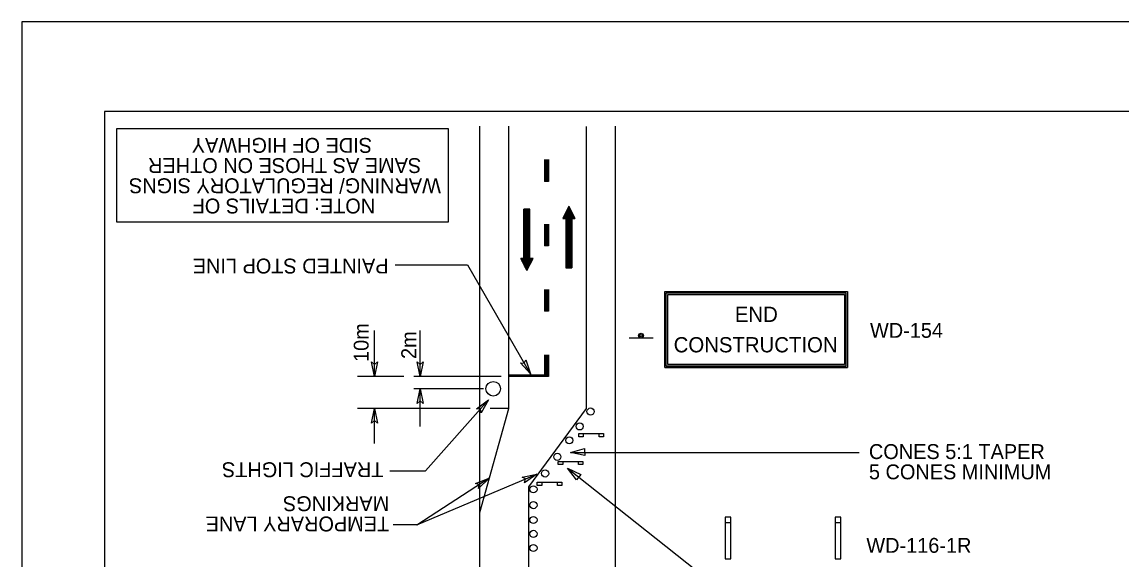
# Model space of a CAD drawing. Extents: x 1062 to 1288, y 239 to 518.
# Drawn here: x 1071.6 to 1204.5, y 453 to 517.9 of the extents above; entities that cross this region are included whole.
import ezdxf

# ---------------------------------------------------------------- set-up
doc = ezdxf.new("R2010")
doc.units = 0
for name, color, linetype in [('Level 10', 7, 'Continuous'), ('Level 17', 7, 'Continuous'), ('Level 44', 7, 'Continuous'), ('Level 5', 7, 'Continuous'), ('Level 60', 7, 'Continuous'), ('Level 7', 7, 'Continuous')]:
    doc.layers.add(name, color=color, linetype=linetype)

# ---------------------------------------------------------------- blocks, each defined once
blk = doc.blocks.new('TAH01')
at = {"layer": 'Level 5'}
blk.add_lwpolyline([(0, 0), (-3, -0.62), (-2.504, 0), (-3, 0.62)], close=True, dxfattribs=at)
blk = doc.blocks.new('LT1')
at = {"layer": 'Level 5'}
blk.add_blockref('TAH01', (0, 0), dxfattribs=at)

msp = doc.modelspace()

# ---------------------------------------------------------------- linework, layer by layer
at = {"layer": 'Level 10'}
for p, q in [((1126.93, 458.61), (1126.93, 505.33)), ((1130.44, 471.19), (1130.44, 505.33)), ((1139.81, 471.19), (1139.81, 505.3)), ((1143.33, 449.55), (1143.33, 505.33)), ((1132.25, 489.35), (1132.25, 495.29)), ((1132.99, 495.29), (1132.25, 495.29)), ((1132.25, 488.6), (1132.25, 495.29)), ((1132.34, 488.42), (1132.34, 495.29)), ((1132.43, 488.23), (1132.43, 495.29)), ((1132.53, 488.05), (1132.53, 495.29)), ((1132.62, 487.86), (1132.62, 495.29)), ((1132.71, 488.05), (1132.71, 495.29)), ((1132.81, 488.23), (1132.81, 495.29)), ((1132.9, 488.42), (1132.9, 495.29)), ((1132.99, 489.35), (1132.99, 495.29)), ((1132.99, 488.6), (1132.99, 495.29)), ((1137.69, 495.64), (1136.95, 494.16)), ((1137.13, 494.53), (1137.13, 494.16)), ((1137.23, 494.71), (1137.23, 494.16)), ((1137.32, 494.9), (1137.32, 488.22)), ((1137.41, 495.08), (1137.41, 488.22)), ((1137.51, 495.27), (1137.51, 488.22)), ((1137.6, 495.45), (1137.6, 488.22)), ((1137.69, 495.64), (1137.69, 488.22)), ((1137.69, 495.64), (1138.43, 494.16)), ((1137.79, 495.45), (1137.79, 488.22)), ((1137.88, 495.27), (1137.88, 488.22)), ((1137.97, 495.08), (1137.97, 488.22)), ((1138.06, 494.9), (1138.06, 488.22)), ((1138.16, 494.71), (1138.16, 494.16)), ((1138.25, 494.53), (1138.25, 494.16)), ((1136.95, 494.16), (1137.32, 494.16)), ((1137.04, 494.34), (1137.04, 494.16)), ((1137.32, 494.16), (1137.32, 488.22)), ((1138.06, 494.16), (1138.06, 488.22)), ((1138.06, 494.16), (1138.43, 494.16)), ((1138.34, 494.34), (1138.34, 494.16)), ((1132.62, 487.86), (1131.88, 489.35)), ((1132.25, 489.35), (1131.88, 489.35)), ((1131.97, 489.16), (1131.97, 489.35)), ((1132.06, 488.98), (1132.06, 489.35)), ((1132.15, 488.79), (1132.15, 489.35)), ((1132.62, 487.86), (1133.36, 489.35)), ((1133.36, 489.35), (1132.99, 489.35)), ((1133.08, 488.79), (1133.08, 489.35)), ((1133.18, 488.98), (1133.18, 489.35)), ((1133.27, 489.16), (1133.27, 489.35)), ((1116.67, 488.58), (1125.43, 488.55)), ((1125.43, 488.55), (1133.23, 475.06)), ((1137.32, 488.22), (1138.06, 488.22)), ((1114.19, 475.06), (1114.19, 480.62)), ((1119.71, 475.06), (1119.71, 480.62)), ((1117.74, 475.06), (1112.12, 475.06)), ((1129.52, 475.06), (1118.94, 475.06)), ((1134.73, 475.23), (1130.44, 475.23)), ((1134.73, 475.18), (1130.44, 475.18)), ((1134.73, 475.12), (1130.44, 475.12)), ((1134.73, 475.06), (1130.44, 475.06)), ((1127.38, 473.57), (1118.94, 473.57)), ((1119.71, 469), (1119.71, 473.57)), ((1120.34, 463.64), (1127.97, 472.22)), ((1125.77, 471.19), (1112.12, 471.19)), ((1114.19, 466.96), (1114.19, 471.19)), ((1126.93, 458.61), (1130.44, 471.19)), ((1130.44, 471.19), (1128.16, 471.19)), ((1132.84, 461.72), (1139.81, 471.19)), ((1116.06, 463.64), (1120.34, 463.64)), ((1128.06, 462.78), (1119.29, 457.1)), ((1119.31, 457.11), (1133.81, 463.24)), ((1126.93, 449.55), (1126.93, 459)), ((1119.29, 457.11), (1116.46, 457.11))]:
    msp.add_line(p, q, dxfattribs=at)
for centre in [(1140.32, 470.82), (1139, 469.03), (1137.75, 467.34), (1136.3, 465.35), (1134.82, 463.34), (1133.41, 461.42), (1133.41, 459.51), (1133.41, 457.71), (1133.41, 456.03), (1133.41, 454.32)]:
    msp.add_circle(centre, 0.434, dxfattribs=at)
at = {"layer": 'Level 17'}
msp.add_line((1149.29, 476.14), (1171.37, 476.14), dxfattribs=at)
for points in [[(1149.29, 485.34), (1171.37, 485.34), (1171.37, 476.14), (1149.29, 476.14)], [(1149.48, 485.16), (1171.19, 485.16), (1171.19, 476.32), (1149.48, 476.32)], [(1149.66, 484.97), (1171.01, 484.97), (1171.01, 476.51), (1149.66, 476.51)]]:
    msp.add_lwpolyline(points, close=True, dxfattribs=at)
at = {"layer": 'Level 44'}
for p, q in [((1135.25, 498.65), (1134.73, 498.65)), ((1135.25, 490.87), (1134.73, 490.87)), ((1135.25, 482.96), (1134.73, 482.96)), ((1147.87, 479.68), (1144.97, 479.68)), ((1135.25, 475.05), (1134.73, 475.05))]:
    msp.add_line(p, q, dxfattribs=at)
for points in [[(1134.73, 501.29), (1134.73, 498.65)], [(1134.82, 501.29), (1134.82, 498.65)], [(1134.9, 501.29), (1134.9, 498.65)], [(1134.99, 501.29), (1134.99, 498.65)], [(1135.08, 501.29), (1135.08, 498.65)], [(1135.17, 501.29), (1135.17, 498.65)], [(1135.25, 501.29), (1135.25, 498.65)], [(1134.73, 493.5), (1134.73, 490.87)], [(1134.82, 493.5), (1134.82, 490.87)], [(1134.9, 493.5), (1134.9, 490.87)], [(1134.99, 493.5), (1134.99, 490.87)], [(1135.08, 493.5), (1135.08, 490.87)], [(1135.17, 493.5), (1135.17, 490.87)], [(1135.25, 493.5), (1135.25, 490.87)], [(1134.73, 485.6), (1134.73, 482.96)], [(1134.82, 485.6), (1134.82, 482.96)], [(1134.9, 485.6), (1134.9, 482.96)], [(1134.99, 485.6), (1134.99, 482.96)], [(1135.08, 485.6), (1135.08, 482.96)], [(1135.17, 485.6), (1135.17, 482.96)], [(1135.25, 485.6), (1135.25, 482.96)], [(1134.73, 477.69), (1134.73, 475.05)], [(1134.82, 477.69), (1134.82, 475.05)], [(1134.9, 477.69), (1134.9, 475.05)], [(1134.99, 477.69), (1134.99, 475.05)], [(1135.08, 477.69), (1135.08, 475.05)], [(1135.17, 477.69), (1135.17, 475.05)], [(1135.25, 477.69), (1135.25, 475.05)]]:
    msp.add_lwpolyline(points, dxfattribs=at)
for centre, radius in [((1146.42, 480), 0.29), ((1146.42, 480), 0.145), ((1128.55, 473.58), 0.878)]:
    msp.add_circle(centre, radius, dxfattribs=at)
at = {"layer": 'Level 5'}
for p, q in [((1138.89, 467.78), (1138.89, 468.15)), ((1138.89, 468.15), (1141.87, 468.15)), ((1139.41, 468.14), (1139.41, 467.78)), ((1141.34, 467.78), (1141.34, 468.15)), ((1141.87, 468.15), (1141.87, 467.78)), ((1139.41, 467.78), (1138.89, 467.78)), ((1141.87, 467.78), (1141.34, 467.77)), ((1136.42, 464.43), (1136.42, 464.8)), ((1136.42, 464.8), (1139.4, 464.8)), ((1136.95, 464.43), (1136.42, 464.43)), ((1136.95, 464.8), (1136.95, 464.43)), ((1138.88, 464.43), (1138.88, 464.8)), ((1139.4, 464.43), (1138.88, 464.43)), ((1139.4, 464.8), (1139.4, 464.43)), ((1132.84, 401.62), (1132.84, 461.72)), ((1133.88, 461.9), (1133.88, 462.27)), ((1133.88, 462.27), (1136.86, 462.27)), ((1134.41, 461.9), (1133.88, 461.9)), ((1134.41, 462.27), (1134.41, 461.9)), ((1136.34, 461.9), (1136.34, 462.27)), ((1136.86, 461.9), (1136.34, 461.9)), ((1136.86, 462.27), (1136.86, 461.9)), ((1157.28, 457.36), (1156.59, 457.36)), ((1170.6, 457.36), (1169.91, 457.36))]:
    msp.add_line(p, q, dxfattribs=at)
for points in [[(1156.59, 453), (1157.28, 453), (1157.28, 458.05), (1156.59, 458.05)], [(1169.91, 453), (1170.6, 453), (1170.6, 458.05), (1169.91, 458.05)]]:
    msp.add_lwpolyline(points, close=True, dxfattribs=at)
at = {"layer": 'Level 60'}
for points in [[(1287.56, 517.93), (1071.56, 517.93), (1071.56, 238.93), (1287.56, 238.93)], [(1268.44, 507.12), (1081.56, 507.12), (1081.56, 249.74), (1268.44, 249.74)]]:
    msp.add_lwpolyline(points, close=True, dxfattribs=at)
at = {"layer": 'Level 7'}
for p, q in [((1137.88, 465.87), (1172.78, 465.88)), ((1137.53, 463.96), (1154.29, 450.66))]:
    msp.add_line(p, q, dxfattribs=at)
for points in [[(1083.02, 505.06), (1123.11, 505.06), (1123.11, 493.74), (1083.02, 493.74)], [(1139.61, 465.49), (1137.88, 465.87), (1139.59, 466.35)], [(1138.6, 462.55), (1137.53, 463.96), (1139.14, 463.23)]]:
    msp.add_lwpolyline(points, close=True, dxfattribs=at)

# ---------------------------------------------------------------- block references
at = {"layer": 'Level 5'}
for p, xscale, yscale, rotation in [((1114.19, 475.06), 0.5856406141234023, 0.5856406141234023, -90), ((1119.71, 475.06), 0.5856406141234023, 0.5856406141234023, -90), ((1133.04, 475.39), 0.5856406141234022, 0.5856406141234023, -59.95725484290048), ((1119.71, 473.57), 0.5856406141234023, 0.5856406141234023, 90), ((1127.97, 472.22), 0.5856406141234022, 0.5856406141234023, 48.33828125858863), ((1114.19, 471.19), 0.5856406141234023, 0.5856406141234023, 90), ((1128.06, 462.78), 0.5856406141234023, 0.5856406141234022, 32.93109763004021), ((1133.81, 463.24), 0.5856406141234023, 0.5856406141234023, 22.894415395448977)]:
    msp.add_blockref('LT1', p, dxfattribs=dict(at, xscale=xscale, yscale=yscale, rotation=rotation))

# ---------------------------------------------------------------- texts
at = {"layer": 'Level 10'}
for s, rotation, p in [('PAINTED STOP LINE', 180, (1115.89, 489.32)), ('10m', 90, (1113.48, 476.82)), ('2m', 90, (1119.23, 477.18)), ('TRAFFIC LIGHTS', 180, (1115.27, 464.69)), ('MARKINGS', 180, (1115.97, 460.58)), ('TEMPORARY LANE', 180, (1115.97, 458.13))]:
    msp.add_text(s, height=1.8, rotation=rotation, dxfattribs=at).set_placement(p)
for s, p in [('WD-154', (1174.11, 479.74)), ('CONES 5:1 TAPER', (1173.98, 465.08)), ('5 CONES MINIMUM', (1173.98, 462.63)), ('WD-116-1R', (1173.67, 453.74))]:
    msp.add_text(s, height=1.8, dxfattribs=at).set_placement(p)
at = {"layer": 'Level 17'}
for s, p in [('END', (1157.77, 481.66)), ('CONSTRUCTION', (1150.37, 477.98))]:
    msp.add_text(s, height=1.84, rotation=360, dxfattribs=at).set_placement(p)
at = {"layer": 'Level 7'}
for s, p in [('SIDE OF HIGHWAY', (1113.89, 503.91)), ('SAME AS THOSE ON OTHER ', (1119.84, 501.47)), ('WARNING/ REGULATORY SIGNS ', (1122.22, 499.03)), ('NOTE: DETAILS OF ', (1114.27, 496.58))]:
    msp.add_text(s, height=1.8, rotation=180, dxfattribs=at).set_placement(p)

doc.saveas('drawing.dxf')
